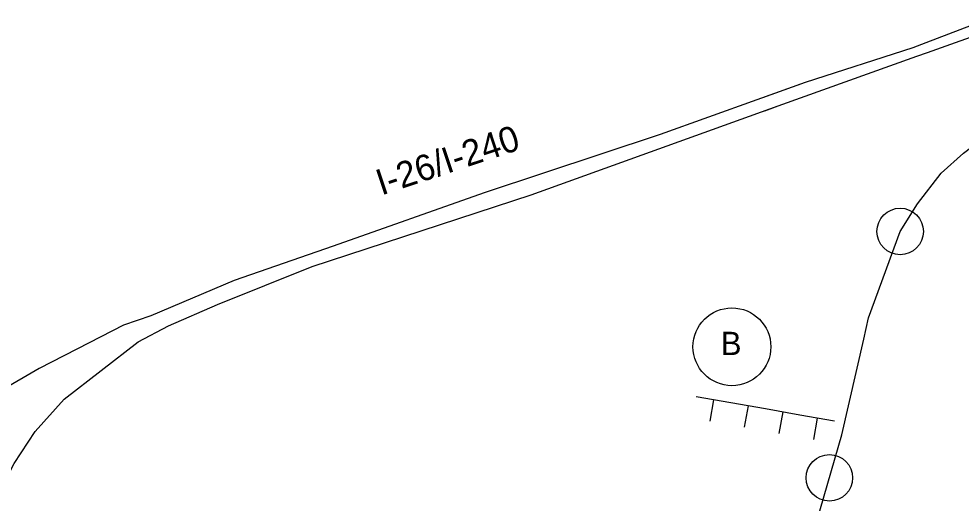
# Model space of a CAD drawing. Extents: x 886234 to 968767, y 455416 to 684046.
# Drawn here: x 911897 to 916452, y 514526 to 516868 of the extents above; entities that cross this region are included whole.
import ezdxf

# ---------------------------------------------------------------- set-up
doc = ezdxf.new("R2010")
doc.units = 0
doc.layers.add('TC DEV SIGN', color=7, linetype='Continuous')
doc.layers.add('TC LABEL TEXT', color=7, linetype='Continuous')

msp = doc.modelspace()

# ---------------------------------------------------------------- linework, layer by layer
at = {"layer": 'TC DEV SIGN'}
for p, q in [((915338.3, 515011.5), (915171.1, 515041)), ((915254.7, 515026.3), (915236.4, 514922.6)), ((915505.5, 514982), (915338.3, 515011.5)), ((915421.9, 514996.8), (915403.6, 514893.1)), ((915672.7, 514952.5), (915505.5, 514982)), ((915589.1, 514967.3), (915570.8, 514863.6)), ((915839.9, 514923.1), (915672.7, 514952.5)), ((915756.3, 514937.8), (915738.1, 514834.1))]:
    msp.add_line(p, q, dxfattribs=at)
at = {"layer": 'TC LABEL TEXT'}
for points in [[(916599, 516868.2), (916501, 516835.2), (916280.9, 516751.4)], [(916289.1, 516705.7), (916610.5, 516819.2)], [(916280.9, 516751.4), (916218.6, 516727.7), (915697.5, 516560.8), (914997.4, 516308.8), (914146.2, 516026.6), (913415.9, 515769.6), (912937.4, 515603.3), (912534.4, 515431.9), (912403.5, 515386.5)], [(916280.9, 516751.4), (916218.6, 516727.7), (915697.5, 516560.8), (915492.3, 516486.9)], [(912474, 515305.9), (912620.5, 515383.5), (912856.8, 515487.3), (913314.5, 515670.6), (914372.8, 516016.5), (915567.7, 516447.7), (916238.2, 516687.8), (916289.1, 516705.7)], [(915502.4, 516424.1), (915567.7, 516447.7), (916238.2, 516687.8), (916289.1, 516705.7)], [(915755, 514440), (915874.8, 514857.4), (915981.8, 515319.3), (916004.3, 515422.6), (916157.1, 515840.2), (916240.5, 515973.7), (916355.4, 516122), (916462.9, 516218.4), (916590.8, 516314.7), (916744.7, 516400)], [(912403.5, 515386.5), (912237.2, 515300.9), (911994.7, 515177.3)], [(911557.3, 513975.4), (911683.2, 514303), (911778.9, 514534.8), (911874.4, 514718.1), (911975.3, 514872.5), (912116.4, 515028.7), (912474, 515305.9)], [(911994.7, 515177.3), (911809.1, 515069), (911587.5, 514922.9), (911365.9, 514751.5)]]:
    msp.add_lwpolyline(points, dxfattribs=at)
for centre, radius in [((916157.1, 515840.2), 112.5), ((916157.1, 515840.2), 112.5), ((915343.7, 515282.5), 188.1), ((915814.9, 514648.7), 112.5), ((915814.9, 514648.7), 112.5)]:
    msp.add_circle(centre, radius, dxfattribs=at)

# ---------------------------------------------------------------- texts
msp.add_text('I-26/I-240', height=125, rotation=18.3431, dxfattribs=at).set_placement((913649.1, 516013.7))
msp.add_text('B', height=112.5, dxfattribs=at).set_placement((915289.8, 515242.6))

doc.saveas('drawing.dxf')
